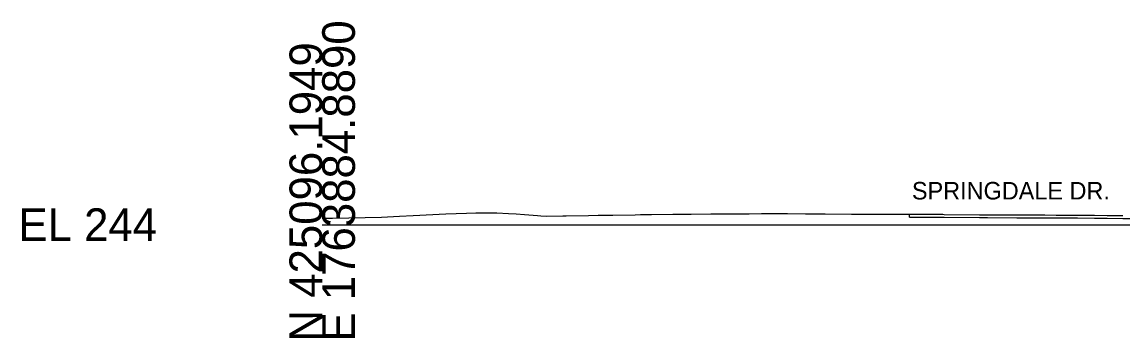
# Model space of a CAD drawing. Extents: x -26 to 3203, y -11010 to 4024.
# Drawn here: x 2974.3 to 3068.5, y -3009.7 to -2982.7 of the extents above; entities that cross this region are included whole.
import ezdxf

# ---------------------------------------------------------------- set-up
doc = ezdxf.new("R2010")
doc.units = 0
for name, color, linetype in [('Default', 7, 'Continuous'), ('Exist Cross Section Cell', 7, 'Continuous'), ('Exist XS Ground Line', 7, 'Continuous'), ('Prop CMT Pvmt Course 1', 7, 'Continuous'), ('Prop XS SE Text', 7, 'Continuous'), ('Scratch_Level_0', 7, 'Continuous')]:
    doc.layers.add(name, color=color, linetype=linetype)

msp = doc.modelspace()

# ---------------------------------------------------------------- linework, layer by layer
at = {"layer": 'Exist Cross Section Cell'}
msp.add_line((3000, -3000), (3100, -3000), dxfattribs=at)
at = {"layer": 'Exist XS Ground Line'}
msp.add_lwpolyline([(3000, -2999.44), (3000.086, -2999.439), (3000.886, -2999.43), (3005.071, -2999.369), (3006.616, -2999.28), (3007.772, -2999.222), (3010.59, -2999.078), (3012.364, -2999.018), (3013.155, -2998.996), (3014.451, -2998.992), (3014.944, -2998.998), (3015.942, -2999.03), (3016.587, -2999.061), (3017.324, -2999.118), (3018.42, -2999.206), (3018.706, -2999.236), (3019.171, -2999.28), (3020.608, -2999.254), (3020.873, -2999.25), (3022.798, -2999.212), (3023.608, -2999.199), (3024.887, -2999.176), (3026.778, -2999.144), (3027.235, -2999.136), (3028.173, -2999.12), (3030.006, -2999.103), (3031.589, -2999.092), (3033.264, -2999.083), (3033.475, -2999.082), (3033.719, -2999.082), (3035.299, -2999.081), (3036.546, -2999.058), (3037.586, -2999.046), (3039.821, -2999.049), (3041.379, -2999.059), (3043.037, -2999.083), (3045.315, -2999.11), (3045.877, -2999.113), (3046.442, -2999.113), (3047.698, -2999.114), (3049.275, -2999.111), (3049.431, -2999.112), (3049.556, -2999.112), (3051.212, -2999.113), (3053.101, -2999.114), (3053.124, -2999.114), (3053.245, -2999.115), (3056.27, -2999.145), (3056.578, -2999.149), (3056.932, -2999.148), (3059.441, -2999.152), (3060.781, -2999.159), (3061.853, -2999.168), (3062.823, -2999.172), (3063.712, -2999.175), (3064.649, -2999.175), (3066.086, -2999.188), (3067.174, -2999.202), (3068.538, -2999.215)], dxfattribs=at)
msp.add_lwpolyline([(3000, -2999.44), (3000.086, -2999.439), (3000.886, -2999.43), (3005.071, -2999.369), (3006.616, -2999.28), (3007.772, -2999.222), (3010.59, -2999.078), (3012.364, -2999.018), (3013.155, -2998.996), (3014.451, -2998.992), (3014.944, -2998.998), (3015.942, -2999.03), (3016.587, -2999.061), (3017.324, -2999.118), (3018.42, -2999.206), (3018.706, -2999.236), (3019.171, -2999.28), (3020.608, -2999.254), (3020.873, -2999.25), (3022.798, -2999.212), (3023.608, -2999.199), (3024.887, -2999.176), (3026.778, -2999.144), (3027.235, -2999.136), (3028.173, -2999.12), (3030.006, -2999.103), (3031.589, -2999.092), (3033.264, -2999.083), (3033.475, -2999.082), (3033.719, -2999.082), (3035.299, -2999.081), (3036.546, -2999.058), (3037.586, -2999.046), (3039.821, -2999.049), (3041.379, -2999.059), (3043.037, -2999.083), (3045.315, -2999.11), (3045.877, -2999.113), (3046.442, -2999.113), (3047.698, -2999.114), (3049.275, -2999.111), (3049.431, -2999.112), (3049.556, -2999.112), (3051.212, -2999.113), (3053.101, -2999.114), (3053.124, -2999.114), (3053.245, -2999.115), (3056.27, -2999.145), (3056.578, -2999.149), (3056.932, -2999.148), (3059.441, -2999.152), (3060.781, -2999.159), (3061.853, -2999.168), (3062.823, -2999.172), (3063.712, -2999.175), (3064.649, -2999.175), (3066.086, -2999.188), (3067.174, -2999.202), (3068.538, -2999.215)], dxfattribs=at)
msp.add_lwpolyline([(3000, -2999.44), (3000.086, -2999.439), (3000.886, -2999.43), (3005.071, -2999.369), (3006.616, -2999.28), (3007.772, -2999.222), (3010.59, -2999.078), (3012.364, -2999.018), (3013.155, -2998.996), (3014.451, -2998.992), (3014.944, -2998.998), (3015.942, -2999.03), (3016.587, -2999.061), (3017.324, -2999.118), (3018.42, -2999.206), (3018.706, -2999.236), (3019.171, -2999.28), (3020.608, -2999.254), (3020.873, -2999.25), (3022.798, -2999.212), (3023.608, -2999.199), (3024.887, -2999.176), (3026.778, -2999.144), (3027.235, -2999.136), (3028.173, -2999.12), (3030.006, -2999.103), (3031.589, -2999.092), (3033.264, -2999.083), (3033.475, -2999.082), (3033.719, -2999.082), (3035.299, -2999.081), (3036.546, -2999.058), (3037.586, -2999.046), (3039.821, -2999.049), (3041.379, -2999.059), (3043.037, -2999.083), (3045.315, -2999.11), (3045.877, -2999.113), (3046.442, -2999.113), (3047.698, -2999.114), (3049.275, -2999.111), (3049.431, -2999.112), (3049.556, -2999.112), (3051.212, -2999.113), (3053.101, -2999.114), (3053.124, -2999.114), (3053.245, -2999.115), (3056.27, -2999.145), (3056.578, -2999.149), (3056.932, -2999.148), (3059.441, -2999.152), (3060.781, -2999.159), (3061.853, -2999.168), (3062.823, -2999.172), (3063.712, -2999.175), (3064.649, -2999.175), (3066.086, -2999.188), (3067.174, -2999.202), (3068.538, -2999.215)], dxfattribs=at)
msp.add_lwpolyline([(3000, -2999.44), (3000.086, -2999.439), (3000.886, -2999.43), (3005.071, -2999.369), (3006.616, -2999.28), (3007.772, -2999.222), (3010.59, -2999.078), (3012.364, -2999.018), (3013.155, -2998.996), (3014.451, -2998.992), (3014.944, -2998.998), (3015.942, -2999.03), (3016.587, -2999.061), (3017.324, -2999.118), (3018.42, -2999.206), (3018.706, -2999.236), (3019.171, -2999.28), (3020.608, -2999.254), (3020.873, -2999.25), (3022.798, -2999.212), (3023.608, -2999.199), (3024.887, -2999.176), (3026.778, -2999.144), (3027.235, -2999.136), (3028.173, -2999.12), (3030.006, -2999.103), (3031.589, -2999.092), (3033.264, -2999.083), (3033.475, -2999.082), (3033.719, -2999.082), (3035.299, -2999.081), (3036.546, -2999.058), (3037.586, -2999.046), (3039.821, -2999.049), (3041.379, -2999.059), (3043.037, -2999.083), (3045.315, -2999.11), (3045.877, -2999.113), (3046.442, -2999.113), (3047.698, -2999.114), (3049.275, -2999.111), (3049.431, -2999.112), (3049.556, -2999.112), (3051.212, -2999.113), (3053.101, -2999.114), (3053.124, -2999.114), (3053.245, -2999.115), (3056.27, -2999.145), (3056.578, -2999.149), (3056.932, -2999.148), (3059.441, -2999.152), (3060.781, -2999.159), (3061.853, -2999.168), (3062.823, -2999.172), (3063.712, -2999.175), (3064.649, -2999.175), (3066.086, -2999.188), (3067.174, -2999.202), (3068.538, -2999.215)], dxfattribs=at)
msp.add_lwpolyline([(3000, -2999.44), (3000.086, -2999.439), (3000.886, -2999.43), (3005.071, -2999.369), (3006.616, -2999.28), (3007.772, -2999.222), (3010.59, -2999.078), (3012.364, -2999.018), (3013.155, -2998.996), (3014.451, -2998.992), (3014.944, -2998.998), (3015.942, -2999.03), (3016.587, -2999.061), (3017.324, -2999.118), (3018.42, -2999.206), (3018.706, -2999.236), (3019.171, -2999.28), (3020.608, -2999.254), (3020.873, -2999.25), (3022.798, -2999.212), (3023.608, -2999.199), (3024.887, -2999.176), (3026.778, -2999.144), (3027.235, -2999.136), (3028.173, -2999.12), (3030.006, -2999.103), (3031.589, -2999.092), (3033.264, -2999.083), (3033.475, -2999.082), (3033.719, -2999.082), (3035.299, -2999.081), (3036.546, -2999.058), (3037.586, -2999.046), (3039.821, -2999.049), (3041.379, -2999.059), (3043.037, -2999.083), (3045.315, -2999.11), (3045.877, -2999.113), (3046.442, -2999.113), (3047.698, -2999.114), (3049.275, -2999.111), (3049.431, -2999.112), (3049.556, -2999.112), (3051.212, -2999.113), (3053.101, -2999.114), (3053.124, -2999.114), (3053.245, -2999.115), (3056.27, -2999.145), (3056.578, -2999.149), (3056.932, -2999.148), (3059.441, -2999.152), (3060.781, -2999.159), (3061.853, -2999.168), (3062.823, -2999.172), (3063.712, -2999.175), (3064.649, -2999.175), (3066.086, -2999.188), (3067.174, -2999.202), (3068.538, -2999.215)], dxfattribs=at)
at = {"layer": 'Prop CMT Pvmt Course 1'}
for points in [[(3050.271, -2999.112), (3051.212, -2999.113), (3053.101, -2999.114), (3053.124, -2999.114), (3053.245, -2999.115), (3056.27, -2999.145), (3056.578, -2999.149), (3056.932, -2999.148), (3059.441, -2999.152), (3060.781, -2999.159), (3061.853, -2999.168), (3062.823, -2999.172), (3063.712, -2999.175), (3064.649, -2999.175), (3066.086, -2999.188), (3067.174, -2999.202), (3068.538, -2999.215)], [(3050.271, -2999.362), (3050.271, -2999.112)], [(3050.271, -2999.362), (3051.212, -2999.363), (3053.101, -2999.364), (3053.124, -2999.364), (3053.245, -2999.365), (3056.27, -2999.395), (3056.578, -2999.399), (3056.932, -2999.398), (3059.441, -2999.402), (3060.781, -2999.409), (3061.853, -2999.418), (3062.823, -2999.422), (3063.712, -2999.425), (3064.649, -2999.425), (3066.086, -2999.438), (3067.174, -2999.452), (3068.538, -2999.465), (3069.431, -2999.468), (3069.998, -2999.463)]]:
    msp.add_lwpolyline(points, dxfattribs=at)

# ---------------------------------------------------------------- texts
at = {"layer": 'Default'}
msp.add_text('-', height=0.0001, dxfattribs=at).set_placement((3000, -3000))
at = {"layer": 'Exist Cross Section Cell'}
for s, p in [('E 1763884.8890', (3002.8, -3010)), ('N 425096.1949', (3000, -3010))]:
    msp.add_text(s, height=2.8, rotation=90, dxfattribs=at).set_placement(p)
msp.add_text('EL 244', height=2.8, dxfattribs=at).set_placement((2974, -3001.4))
at = {"layer": 'Prop XS SE Text'}
msp.add_text('SPRINGDALE DR.', height=1.5, rotation=360, dxfattribs=at).set_placement((3050.475, -2997.844))
at = {"layer": 'Scratch_Level_0'}
for s, p in [('Exterior Boundary', (3050.112, -2999.122)), ('LT_Res Edge', (3050.17, -2999.122))]:
    msp.add_text(s, height=0.02, dxfattribs=at).set_placement(p)

doc.saveas('drawing.dxf')
